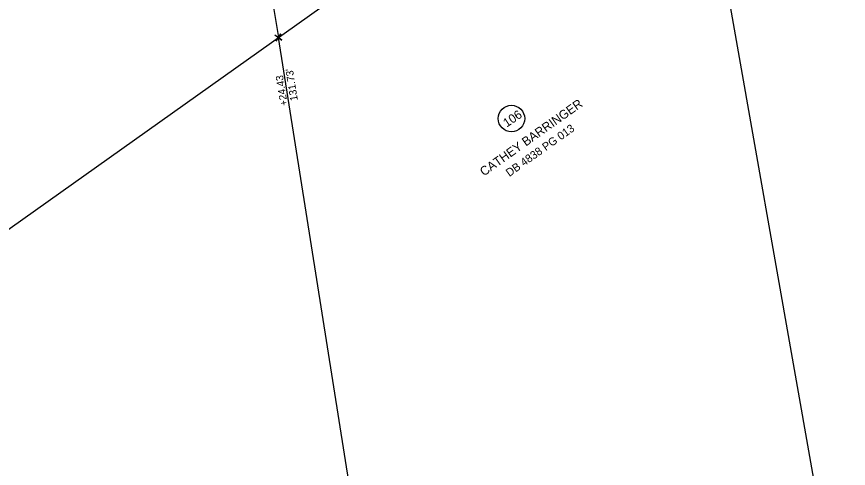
# Model space of a CAD drawing. Extents: x 1577032 to 1581865, y 611492 to 615011.
# Drawn here: x 1578479.3 to 1578946.8, y 612106.9 to 612360.6 of the extents above; entities that cross this region are included whole.
import ezdxf

# ---------------------------------------------------------------- set-up
doc = ezdxf.new("R2010")
doc.units = 0
for name, color, linetype in [('Exist Property Corner CELL', 7, 'Continuous'), ('Exist Property Deed Book Text', 7, 'Continuous'), ('Exist Property Line', 7, 'Continuous'), ('Exist Property Owner Text', 7, 'Continuous'), ('Exist Property Tie Line', 7, 'Continuous'), ('Exist Property Tie Line Text', 7, 'Continuous'), ('Exist Right of Way Line', 7, 'Continuous'), ('Old_Level_25', 7, 'Continuous')]:
    doc.layers.add(name, color=color, linetype=linetype)

msp = doc.modelspace()

# ---------------------------------------------------------------- linework, layer by layer
at = {"layer": 'Exist Property Corner CELL'}
msp.add_line((1578626.37, 612348.87), (1578626.37, 612348.87), dxfattribs=at)
msp.add_lwpolyline([(1578624.35, 612350.34), (1578628.39, 612347.4), (1578626.37, 612348.87), (1578627.84, 612350.89), (1578624.9, 612346.85)], dxfattribs=at)
at = {"layer": 'Exist Property Line'}
msp.add_line((1578759.97, 611506.51), (1578626.37, 612348.87), dxfattribs=at)
msp.add_lwpolyline([(1579034.3, 611494.43), (1578873.02, 612409.05)], dxfattribs=at)
at = {"layer": 'Exist Property Tie Line'}
msp.add_line((1578605.74, 612478.97), (1578626.37, 612348.87), dxfattribs=at)
at = {"layer": 'Exist Right of Way Line'}
msp.add_line((1578304.92, 612120.6), (1580458.22, 613649.74), dxfattribs=at)
at = {"layer": 'Old_Level_25'}
msp.add_circle((1578757.39, 612303.36), 7.44, dxfattribs=at)

# ---------------------------------------------------------------- texts
at = {"layer": 'Exist Property Deed Book Text'}
msp.add_text('DB 4838 PG 013', height=4.5, rotation=35.38, dxfattribs=at).set_placement((1578756.23, 612270.49))
at = {"layer": 'Exist Property Owner Text'}
msp.add_text('CATHEY BARRINGER', height=5, rotation=35.38, dxfattribs=at).set_placement((1578741.9, 612270.8))
at = {"layer": 'Exist Property Tie Line Text'}
for s, p in [('+24.43', (1578631.65, 612310.83)), ("131.73'", (1578637.35, 612313.65))]:
    msp.add_text(s, height=4.2, rotation=99.0121, dxfattribs=at).set_placement(p)
at = {"layer": 'Old_Level_25'}
msp.add_text('106', height=4.921, rotation=33.9997, dxfattribs=at).set_placement((1578754.76, 612298.28))

doc.saveas('drawing.dxf')
